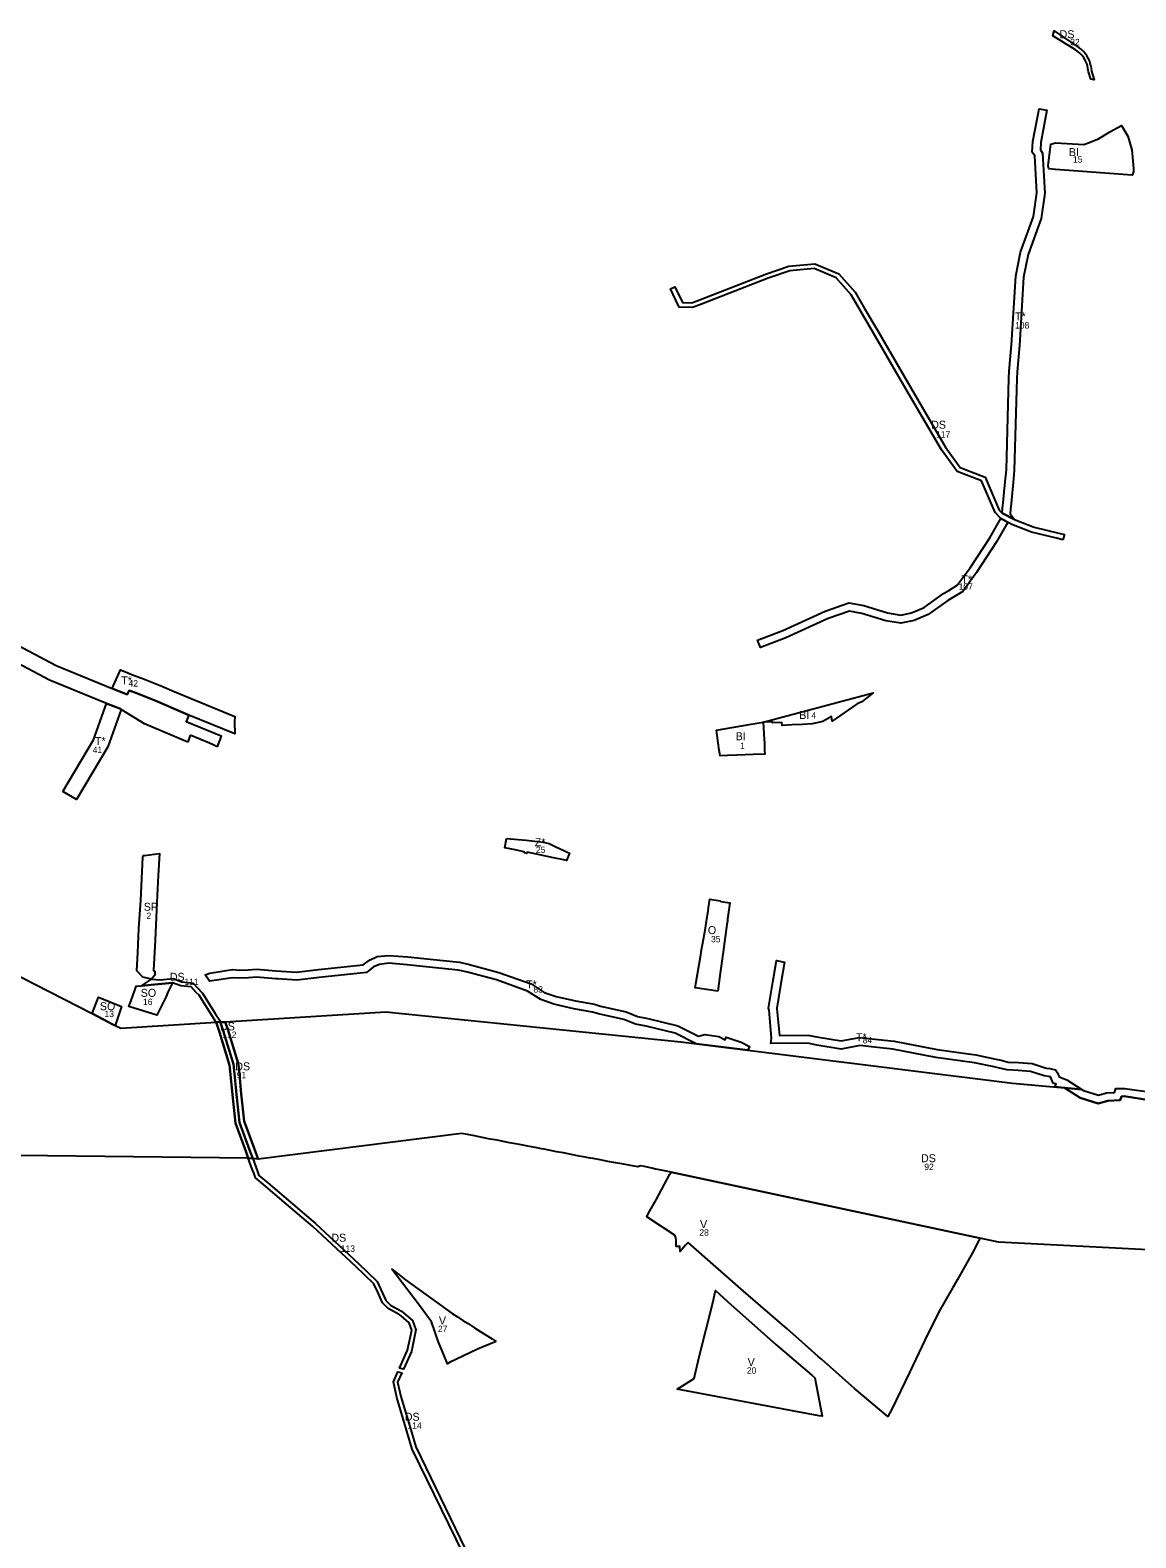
# Model space of a CAD drawing. Extents: x -521621 to -516990, y -1190025 to -1185905.
# Drawn here: x -520236 to -518852, y -1188135 to -1186245 of the extents above; entities that cross this region are included whole.
import ezdxf

# ---------------------------------------------------------------- set-up
doc = ezdxf.new("R2010")
doc.units = 0
for name, color, linetype in [('bydleni_n', 7, 'Continuous'), ('fpl_id', 7, 'Continuous'), ('s_zelen_n', 7, 'Continuous'), ('sm_vyuziti_n', 7, 'Continuous'), ('v_infrastr_n', 7, 'Continuous'), ('vyroba_n', 7, 'Continuous')]:
    doc.layers.add(name, color=color, linetype=linetype)

msp = doc.modelspace()

# ---------------------------------------------------------------- linework, layer by layer
at = {"layer": 'bydleni_n'}
for points in [[(-518960.2, -1186405.1), (-518958.4, -1186388.1), (-518952.3, -1186386.8), (-518916.8, -1186388.7), (-518912.4, -1186387), (-518898.4, -1186381.6), (-518884.4, -1186373), (-518869.8, -1186364.9), (-518861.7, -1186378.4), (-518856.9, -1186395.2), (-518854.7, -1186418.7), (-518854.5, -1186422.8), (-518856.2, -1186427), (-518952.5, -1186420.2), (-518960.7, -1186419), (-518961.4, -1186415.5)], [(-519243.9, -1187111.9), (-519257.2, -1187114.7), (-519269.3, -1187115.4), (-519282.1, -1187116.2), (-519294.8, -1187116.9), (-519295, -1187113.1), (-519306.6, -1187113.6), (-519306.7, -1187112.1), (-519318.4, -1187112.7), (-519180.8, -1187076), (-519188.7, -1187082.3), (-519194.9, -1187087.3), (-519200.6, -1187089.9), (-519232.1, -1187111.3), (-519232.7, -1187105.6)], [(-519374.8, -1187138.6), (-519377.1, -1187122.7), (-519333.6, -1187115.3), (-519318.4, -1187112.7), (-519317.3, -1187134.4), (-519317, -1187139.1), (-519316.8, -1187142.2), (-519316.6, -1187147.9), (-519316.5, -1187152.8), (-519331, -1187153.3), (-519351.3, -1187154.1), (-519363.3, -1187154.5), (-519372.4, -1187154.9), (-519372.4, -1187154.8), (-519373.5, -1187147.6)]]:
    msp.add_lwpolyline(points, close=True, dxfattribs=at)
at = {"layer": 's_zelen_n'}
msp.add_lwpolyline([(-519640.1, -1187258.6), (-519615.3, -1187260.6), (-519594.2, -1187263), (-519586.4, -1187264.7), (-519578.9, -1187268.3), (-519560.9, -1187276.9), (-519564.6, -1187286), (-519568.1, -1187285.3), (-519581.2, -1187282.5), (-519596.5, -1187279.2), (-519613.9, -1187275.5), (-519614.5, -1187277.1), (-519617.5, -1187276.6), (-519617.7, -1187275.1), (-519631.2, -1187272.3), (-519642.2, -1187270.1)], close=True, dxfattribs=at)
at = {"layer": 'sm_vyuziti_n'}
for points in [[(-520103, -1187424.2), (-520101.8, -1187401.5), (-520100.3, -1187371.4), (-520097.7, -1187335.6), (-520095.3, -1187281.8), (-520095, -1187279.6), (-520093.3, -1187279.6), (-520074.5, -1187277.4), (-520076, -1187304.7), (-520077.7, -1187338.3), (-520079.9, -1187386), (-520081.9, -1187423.7), (-520080.3, -1187424.7), (-520080.4, -1187429.6), (-520084.4, -1187434.6), (-520095.2, -1187432.2)], [(-520159, -1187477.9), (-520151.1, -1187457.3), (-520122.2, -1187468.9), (-520130, -1187493), (-520132.3, -1187491.8)]]:
    msp.add_lwpolyline(points, close=True, dxfattribs=at)
for points in [[(-520084.9, -1187441.8), (-520058.1, -1187439.2), (-520064.1, -1187451.2), (-520066.2, -1187456.4), (-520078, -1187480), (-520112.8, -1187468.9), (-520110.1, -1187461.4)], [(-520110.1, -1187461.4), (-520105.5, -1187448.5), (-520103.8, -1187443.7), (-520097.1, -1187443.1), (-520084.9, -1187441.8)]]:
    msp.add_lwpolyline(points, dxfattribs=at)
at = {"layer": 'v_infrastr_n'}
for p, q in [((-518940.9, -1186877.6), (-518943.1, -1186884.1)), ((-520093.3, -1187114.7), (-520122.4, -1187096.8)), ((-520039.2, -1187137.8), (-520093.3, -1187114.7)), ((-520037.7, -1187134.1), (-520039.2, -1187137.8)), ((-520036.1, -1187128.8), (-520037.7, -1187134.1))]:
    msp.add_line(p, q, dxfattribs=at)
for points in [[(-518927.4, -1186270), (-518955.8, -1186252.5), (-518953.9, -1186246.2), (-518922.6, -1186267.6)], [(-518908.2, -1186290.1), (-518907.1, -1186296.6), (-518903.9, -1186307.5), (-518908.2, -1186306.9), (-518911, -1186297.5), (-518911.7, -1186293.4)], [(-519007, -1186864.9), (-519021, -1186857.6), (-519028, -1186850.1), (-519045, -1186810.3), (-519075.6, -1186798.4), (-519095.1, -1186771.4), (-519142.2, -1186690.6), (-519180.2, -1186625.3), (-519196.6, -1186597.2), (-519208.2, -1186577.3), (-519227.2, -1186555.7), (-519254.6, -1186544.3), (-519285.2, -1186547.2), (-519312.1, -1186556.4), (-519395.9, -1186588.8), (-519407, -1186593.1), (-519423.5, -1186592.5), (-519427.8, -1186583.6), (-519434.5, -1186569.6), (-519429.1, -1186567), (-519419.7, -1186586.6), (-519408, -1186587.1), (-519396.9, -1186582.8), (-519314.2, -1186550.8), (-519286.5, -1186541.3), (-519253.7, -1186538.2), (-519223.6, -1186550.7), (-519203.3, -1186573.7), (-519191.4, -1186594.2), (-519175, -1186622.3), (-519137, -1186687.6), (-519090.1, -1186768.1), (-519071.8, -1186793.4), (-519040.5, -1186805.6), (-519022.9, -1186846.8), (-519019.2, -1186850.6), (-519003.8, -1186858.7)], [(-518943.1, -1186884.1), (-518951.3, -1186882.1), (-518982.5, -1186874.5), (-519007, -1186864.9)], [(-519003.8, -1186858.7), (-518979.2, -1186868.2), (-518948, -1186875.8)], [(-518948, -1186875.8), (-518940.9, -1186877.6)], [(-520405, -1186935.1), (-520203.8, -1187041.8), (-520133.6, -1187070.6), (-520115, -1187077.9), (-520112.7, -1187072.8), (-520104.1, -1187076.1), (-520079.2, -1187086), (-520063.8, -1187092.5), (-520037.7, -1187103.7), (-520041.1, -1187111.9), (-519997.2, -1187130), (-519997.3, -1187130.5), (-519997.5, -1187130.9), (-519998.5, -1187133.4)], [(-520122.4, -1187096.8), (-520123.5, -1187096.1), (-520140.9, -1187089.3), (-520212.4, -1187059.9), (-520412.3, -1186953.8)], [(-520001.8, -1187143.5), (-520011.9, -1187138.8), (-520036.1, -1187128.8)], [(-519998.5, -1187133.4), (-519998.6, -1187133.9), (-519999.8, -1187136.8), (-520000.6, -1187139), (-520001.4, -1187141.2), (-520001.8, -1187143.5)], [(-520784.9, -1187157.2), (-520159, -1187477.9), (-520132.3, -1187491.8), (-520130, -1187493), (-520122.9, -1187496.1), (-520003.6, -1187488.8), (-519999.4, -1187501.1), (-519986.8, -1187542.4), (-519985.9, -1187549.9), (-519983.1, -1187579.6), (-519979.3, -1187615.3), (-519966.4, -1187650.5), (-519963.3, -1187659), (-520250.8, -1187655.6)], [(-519395.2, -1187396), (-519394.1, -1187389.3), (-519391.3, -1187373.2), (-519390, -1187365.2), (-519388.2, -1187354), (-519387.5, -1187349.5), (-519386.8, -1187345.3), (-519385.1, -1187334.5), (-519372.3, -1187336.4), (-519371.6, -1187337.6), (-519360.2, -1187339), (-519363, -1187359.7), (-519363.3, -1187362), (-519363.8, -1187366.1), (-519368.5, -1187400.5)], [(-519375.2, -1187449.8), (-519403.5, -1187445.6), (-519402.6, -1187440.6), (-519396.7, -1187404.2), (-519395.6, -1187397.9), (-519395.2, -1187396)], [(-519368.5, -1187400.5), (-519372.2, -1187427.2), (-519375.2, -1187449.8)], [(-520028.4, -1187451.3), (-520034.9, -1187444.5), (-520047.6, -1187443), (-520058.1, -1187439.2), (-520084.9, -1187441.8), (-520097.1, -1187443.1), (-520084.4, -1187434.6), (-520073.6, -1187435.7), (-520057.4, -1187434.1), (-520049.2, -1187437.1), (-520046.4, -1187438.1), (-520032.5, -1187439.7), (-520027.3, -1187445.3), (-520020.8, -1187452.1)], [(-520003.6, -1187488.8), (-520003.8, -1187488.4), (-520008.9, -1187480.3), (-520025, -1187454.8), (-520028.4, -1187451.3)], [(-520020.8, -1187452.1), (-520004.7, -1187477.6), (-519999.7, -1187485.5), (-519999.2, -1187486.2), (-519998.5, -1187488.4), (-520003.6, -1187488.8)], [(-518738.7, -1187779), (-519023.8, -1187764.4), (-519433.9, -1187676.7), (-519450.5, -1187673.5), (-519453.5, -1187672.8), (-519458, -1187671.8), (-519461.7, -1187670.9), (-519467.2, -1187669.7), (-519472.1, -1187668.6), (-519475.5, -1187670.1), (-519486.8, -1187668), (-519495.4, -1187666.4), (-519503.6, -1187664.9), (-519513.2, -1187663.1), (-519522.7, -1187661.3), (-519531.3, -1187659.7), (-519535.2, -1187659), (-519541.3, -1187657.8), (-519548.9, -1187656.4), (-519559.1, -1187654.4), (-519568.5, -1187652.6), (-519577.2, -1187651), (-519587, -1187649.1), (-519592.9, -1187647.9), (-519595.9, -1187647.4), (-519604.1, -1187645.8), (-519613.4, -1187644), (-519623.8, -1187642), (-519636, -1187639.7), (-519642, -1187638.6), (-519651.6, -1187636.7), (-519660.2, -1187635.1), (-519670.3, -1187633.1), (-519680.2, -1187631.2), (-519688.7, -1187629.6), (-519696.3, -1187628.1), (-519951.1, -1187660.2), (-519956.1, -1187646.7), (-519968.5, -1187612.8), (-519972.2, -1187578.6), (-519974.9, -1187548.7), (-519976, -1187540.1), (-519989, -1187497.8), (-519992.3, -1187488.1), (-519790.9, -1187475.7), (-519421.5, -1187513.5), (-519006.3, -1187565.1), (-518941, -1187571), (-518921.5, -1187583.6), (-518898.8, -1187590.5), (-518887, -1187587.1), (-518871.3, -1187586.4), (-518869.6, -1187581.7), (-518866.3, -1187581.6), (-518835.2, -1187586.3)], [(-520003.6, -1187488.8), (-519998.5, -1187488.4)], [(-519998.5, -1187488.4), (-519994.7, -1187499.6), (-519981.9, -1187541.3), (-519980.9, -1187549.3), (-519978.1, -1187579.2), (-519974.4, -1187614.2), (-519961.7, -1187648.8), (-519957.8, -1187659.5), (-519963.3, -1187659), (-519966.4, -1187650.5), (-519979.3, -1187615.3), (-519983.1, -1187579.6), (-519985.9, -1187549.9), (-519986.8, -1187542.4), (-519999.4, -1187501.1), (-520003.6, -1187488.8)], [(-518835.2, -1187586.3), (-518866.3, -1187581.6), (-518869.6, -1187581.7), (-518871.3, -1187586.4), (-518887, -1187587.1), (-518898.8, -1187590.5), (-518921.5, -1187583.6), (-518941, -1187571), (-518919.5, -1187573), (-518917.3, -1187574.4), (-518898.7, -1187580.1), (-518888.6, -1187577.2), (-518878.4, -1187576.7), (-518876.6, -1187571.9), (-518865.7, -1187571.6), (-518833.1, -1187576.5)], [(-519684.7, -1188174.4), (-519758, -1188023.6), (-519764.6, -1188001.2), (-519777.1, -1187959.1), (-519781.6, -1187939.4), (-519776, -1187926.9), (-519771.1, -1187928.1), (-519776.4, -1187939.9), (-519772.2, -1187957.8), (-519759.8, -1187999.7), (-519753.6, -1188021), (-519679.4, -1188173.7)]]:
    msp.add_lwpolyline(points, dxfattribs=at)
for points in [[(-519000.6, -1186682), (-519004, -1186797.1), (-519005.4, -1186812.4), (-519006.7, -1186825.4), (-519008, -1186838.6), (-519008.6, -1186845.6), (-519009.2, -1186851.7), (-519003.8, -1186858.7), (-519019.2, -1186850.6), (-519018.6, -1186844.6), (-519017.9, -1186837.7), (-519016.7, -1186824.5), (-519015.4, -1186811.5), (-519013.9, -1186796.5), (-519010.6, -1186681.7), (-519010.4, -1186672.8), (-519007.3, -1186639.8), (-519002.2, -1186553.8), (-518996.1, -1186523.7), (-518980.1, -1186479), (-518975.6, -1186449.1), (-518978.3, -1186402.7), (-518981.4, -1186398.1), (-518980.6, -1186385), (-518973, -1186343.9), (-518963.1, -1186345.8), (-518970.7, -1186386.2), (-518971.2, -1186395.4), (-518968.5, -1186399.5), (-518965.6, -1186449.6), (-518970.4, -1186481.5), (-518986.4, -1186526.4), (-518992.3, -1186555.1), (-518997.4, -1186640.6), (-519000.4, -1186673.4)], [(-519240.8, -1186973.6), (-519211.2, -1186963.1), (-519192.2, -1186966.6), (-519162.7, -1186975.8), (-519146.1, -1186978.5), (-519132.5, -1186975.8), (-519116.9, -1186969.1), (-519092.6, -1186951.6), (-519085.8, -1186947.5), (-519075.4, -1186941.1), (-519059.4, -1186919.2), (-519034.7, -1186881.5), (-519021, -1186857.6), (-519012.1, -1186862.2), (-519026.2, -1186886.7), (-519051.2, -1186924.9), (-519068.5, -1186948.7), (-519087.1, -1186960), (-519111.9, -1186977.9), (-519129.5, -1186985.4), (-519145.9, -1186988.7), (-519165, -1186985.6), (-519194.7, -1186976.3), (-519210.4, -1186973.4), (-519237, -1186982.9), (-519290, -1187006.8), (-519321.9, -1187019.1), (-519325.5, -1187009.8), (-519293.9, -1186997.6)], [(-520133.6, -1187070.6), (-520123.4, -1187047.1), (-520104.8, -1187054.4), (-520096.8, -1187057.5), (-520071.6, -1187067.5), (-520056, -1187074.1), (-520030, -1187085.2), (-519980.3, -1187105.7), (-519980.7, -1187112.2), (-519980.3, -1187127.3), (-520037.7, -1187103.7), (-520063.8, -1187092.5), (-520079.2, -1187086), (-520104.1, -1187076.1), (-520112.7, -1187072.8), (-520115, -1187077.9)], [(-520195.7, -1187199.5), (-520157.3, -1187134.8), (-520140.9, -1187089.3), (-520123.5, -1187096.1), (-520122.4, -1187096.8), (-520139.1, -1187143.4), (-520178.5, -1187209.7)], [(-519735.7, -1187409.7), (-519698.8, -1187413.4), (-519687.9, -1187415.9), (-519649.6, -1187426.2), (-519609, -1187440.6), (-519592.6, -1187451.4), (-519577.8, -1187456.6), (-519553.7, -1187462), (-519529.8, -1187466.3), (-519522, -1187468.6), (-519489.9, -1187475.9), (-519475.7, -1187481.4), (-519462.8, -1187483.9), (-519425.3, -1187493.2), (-519399.3, -1187506.3), (-519391.7, -1187504.3), (-519374.1, -1187506.8), (-519366.1, -1187510.6), (-519364.7, -1187507.5), (-519346.2, -1187513.6), (-519335.5, -1187519.3), (-519337.5, -1187523.9), (-519402.5, -1187515.9), (-519428.8, -1187502.6), (-519465, -1187493.7), (-519478.4, -1187491.1), (-519492.8, -1187485.5), (-519524.5, -1187478.3), (-519532.1, -1187476.1), (-519555.7, -1187471.8), (-519580.6, -1187466.2), (-519597.1, -1187460.4), (-519613.5, -1187449.6), (-519652.6, -1187435.8), (-519690.3, -1187425.6), (-519700.4, -1187423.3), (-519736.7, -1187419.6), (-519764.5, -1187416.6), (-519787.4, -1187414.9), (-519799.1, -1187416.2), (-519806.3, -1187419.4), (-519815.4, -1187426.6), (-519874.4, -1187432.7), (-519902.6, -1187436.1), (-519926.4, -1187434.5), (-519929.4, -1187434.3), (-519953.1, -1187432.2), (-519963, -1187432.9), (-519974.6, -1187433.6), (-519982.9, -1187432.9), (-520009.1, -1187436.9), (-520012, -1187437.3), (-520017.5, -1187429.2), (-520011.5, -1187427.1), (-519983.2, -1187422.8), (-519974.4, -1187423.6), (-519963.6, -1187423), (-519953, -1187422.2), (-519928.6, -1187424.4), (-519902.8, -1187426), (-519875.5, -1187422.8), (-519819.3, -1187416.9), (-519811.5, -1187410.8), (-519801.7, -1187406.4), (-519787.5, -1187404.9), (-519763.6, -1187406.6)], [(-519306.3, -1187438.7), (-519301.7, -1187411.4), (-519291.8, -1187413.4), (-519296.5, -1187440.4), (-519301.5, -1187470.9), (-519301.2, -1187472.1), (-519298.2, -1187505.3), (-519262.5, -1187504.9), (-519249.3, -1187507.6), (-519220.9, -1187512.2), (-519197.7, -1187508), (-519174.4, -1187510.5), (-519154.5, -1187512.6), (-519100.6, -1187523), (-519067.6, -1187527.6), (-519052.2, -1187529.7), (-519027.2, -1187534.9), (-519020.2, -1187536.4), (-519011.5, -1187538.6), (-518998.6, -1187539.3), (-518981.7, -1187540.5), (-518964.2, -1187546.2), (-518959.5, -1187546.9), (-518952.3, -1187548.3), (-518950, -1187552.2), (-518947.7, -1187557.3), (-518938.1, -1187561), (-518919.5, -1187573), (-518941, -1187571), (-518953.1, -1187569.9), (-518951.6, -1187566.5), (-518955.2, -1187565.1), (-518958.7, -1187557.3), (-518961.2, -1187556.8), (-518966.6, -1187556), (-518983.6, -1187550.4), (-518999.2, -1187549.3), (-519013.1, -1187548.5), (-519022.5, -1187546.1), (-519029.3, -1187544.6), (-519053.8, -1187539.6), (-519069, -1187537.5), (-519102.2, -1187532.8), (-519155.9, -1187522.5), (-519175.4, -1187520.4), (-519197.3, -1187518.1), (-519220.8, -1187522.3), (-519251.1, -1187517.4), (-519262.7, -1187515.1), (-519308.7, -1187515.4), (-519307.9, -1187508.8), (-519311.1, -1187473.6), (-519311.7, -1187471.1)], [(-519992.3, -1187488.1), (-519989, -1187497.8), (-519976, -1187540.1), (-519974.9, -1187548.7), (-519972.2, -1187578.6), (-519968.5, -1187612.8), (-519956.1, -1187646.7), (-519951.1, -1187660.2), (-519957.8, -1187659.5), (-519961.7, -1187648.8), (-519974.4, -1187614.2), (-519978.1, -1187579.2), (-519980.9, -1187549.3), (-519981.9, -1187541.3), (-519994.7, -1187499.6), (-519998.5, -1187488.4)], [(-519957.8, -1187659.5), (-519951.9, -1187675.7), (-519950, -1187680.7), (-519938.7, -1187690.2), (-519879.1, -1187740.9), (-519825.4, -1187791.1), (-519801.9, -1187813.7), (-519790.9, -1187837.6), (-519785.2, -1187843.5), (-519771.6, -1187850.7), (-519757.5, -1187862.4), (-519753.3, -1187874.2), (-519759.1, -1187901.2), (-519769.1, -1187923.5), (-519774, -1187922.2), (-519763.9, -1187899.7), (-519758.5, -1187874.5), (-519761.7, -1187865.3), (-519772, -1187856.8), (-519774.4, -1187854.9), (-519788.2, -1187847.5), (-519795.1, -1187840.5), (-519801.2, -1187827.2), (-519806.1, -1187816.7), (-519828.8, -1187794.7), (-519882.4, -1187744.6), (-519926.7, -1187707), (-519941.9, -1187694.1), (-519954.2, -1187683.7), (-519956.5, -1187677.4), (-519958.3, -1187672.7), (-519963.3, -1187659)]]:
    msp.add_lwpolyline(points, close=True, dxfattribs=at)
for centre, end in [((-518945.2, -1186299), 58.3971), ((-518941.7, -1186295.7), 55.7376)]:
    msp.add_arc(centre, 34, 9.5068, end, dxfattribs=at)
at = {"layer": 'vyroba_n'}
for points in [[(-519273.6, -1187886), (-519288.3, -1187872.8), (-519343.3, -1187825.6), (-519412.6, -1187764.7), (-519415.6, -1187768.2), (-519422.5, -1187776), (-519422.8, -1187770), (-519427.3, -1187769.8), (-519427.6, -1187761.4), (-519428, -1187759.6), (-519428.8, -1187756.1), (-519464.3, -1187732.7), (-519461.9, -1187728.2), (-519452.6, -1187711.2), (-519435.3, -1187679.3), (-519433.9, -1187676.7), (-519046.8, -1187759.5)], [(-519046.8, -1187759.5), (-519047.4, -1187760.7)], [(-519047.4, -1187760.7), (-519047.8, -1187761.5), (-519056, -1187777), (-519075.2, -1187811), (-519080.8, -1187821), (-519098.4, -1187851.5), (-519115.5, -1187886.4), (-519135.2, -1187927.9), (-519157.4, -1187973.7), (-519162.2, -1187983), (-519204.1, -1187947.8), (-519245.6, -1187911), (-519249.5, -1187907.6)], [(-519249.5, -1187907.6), (-519273.6, -1187886)]]:
    msp.add_lwpolyline(points, dxfattribs=at)
for points in [[(-519652.7, -1187889), (-519676.3, -1187898.3), (-519712, -1187915.4), (-519713.9, -1187916.9), (-519718.4, -1187905.7), (-519724.9, -1187889.5), (-519734, -1187864.4), (-519750.2, -1187842.1), (-519783.6, -1187798.4), (-519774.8, -1187805), (-519766.3, -1187811.4), (-519708.1, -1187853.8), (-519701.3, -1187858.1), (-519694.5, -1187862.5), (-519688.1, -1187866.5), (-519679.8, -1187871.8), (-519672.1, -1187876.7), (-519665.3, -1187881), (-519658, -1187885.7)], [(-519266.2, -1187978.5), (-519426, -1187948.6), (-519405, -1187935.4), (-519404.2, -1187931.3), (-519398.5, -1187907.9), (-519381.7, -1187840.3), (-519378, -1187824.9), (-519363.2, -1187838.8), (-519302.7, -1187892.6), (-519257.7, -1187931.2), (-519253.8, -1187934.5), (-519244.5, -1187982.5), (-519248.2, -1187981.9)]]:
    msp.add_lwpolyline(points, close=True, dxfattribs=at)

# ---------------------------------------------------------------- texts
at = {"layer": 'bydleni_n'}
for p in [(-518935.7, -1186403.2), (-519273.3, -1187108.7), (-519352.9, -1187135.3)]:
    msp.add_text('BI', height=10, dxfattribs=at).set_placement(p)
at = {"layer": 'fpl_id'}
for s, p in [('32', (-518934, -1186264.3)), ('15', (-518930.5, -1186411.4)), ('108', (-519003, -1186619.3)), ('117', (-519102, -1186756)), ('107', (-519073.7, -1186946.7)), ('42', (-520113.3, -1187068)), ('4', (-519258.1, -1187108.2)), ('41', (-520158.2, -1187151.4)), ('1', (-519347.4, -1187146.2)), ('25', (-519603.1, -1187276.6)), ('2', (-520090.8, -1187359.4)), ('35', (-519383.8, -1187388.6)), ('111', (-520043.3, -1187442.1)), ('83', (-519606.2, -1187451.6)), ('13', (-520143.4, -1187482.3)), ('16', (-520095.2, -1187467.2)), ('112', (-519996, -1187508.4)), ('84', (-519193.8, -1187515.2)), ('91', (-519977.8, -1187558.9)), ('92', (-519116.7, -1187673.9)), ('28', (-519398.4, -1187756.3)), ('113', (-519847.6, -1187776.5)), ('27', (-519725.8, -1187877)), ('20', (-519338.9, -1187929.2)), ('114', (-519764, -1187998.2))]:
    msp.add_text(s, height=8, dxfattribs=at).set_placement(p)
at = {"layer": 's_zelen_n'}
msp.add_text('Z*', height=10, dxfattribs=at).set_placement((-519604.5, -1187268.1))
at = {"layer": 'sm_vyuziti_n'}
for s, p in [('SP', (-520094.2, -1187349)), ('SO', (-520098, -1187456.9)), ('SO', (-520149.2, -1187473.7))]:
    msp.add_text(s, height=10, dxfattribs=at).set_placement(p)
at = {"layer": 'v_infrastr_n'}
for s, p in [('DS', (-518947.2, -1186255.5)), ('T*', (-519003, -1186609)), ('DS', (-519108.1, -1186744.9)), ('T*', (-519070.3, -1186938.6)), ('T*', (-520122.4, -1187065.4)), ('T*', (-520155.3, -1187141.2)), ('O', (-519387.7, -1187378.3)), ('DS', (-520061.6, -1187436.8)), ('T*', (-519615.4, -1187446.4)), ('DS', (-519998.7, -1187498.9)), ('T*', (-519202.2, -1187512.5)), ('DS', (-519979.6, -1187549)), ('DS', (-519120.8, -1187664.2)), ('DS', (-519859.2, -1187763.8)), ('DS', (-519767.3, -1187988.2))]:
    msp.add_text(s, height=10, dxfattribs=at).set_placement(p)
at = {"layer": 'vyroba_n'}
for p in [(-519397.5, -1187746.8), (-519724.6, -1187867.5), (-519337.9, -1187919.7)]:
    msp.add_text('V', height=10, dxfattribs=at).set_placement(p)

doc.saveas('drawing.dxf')
